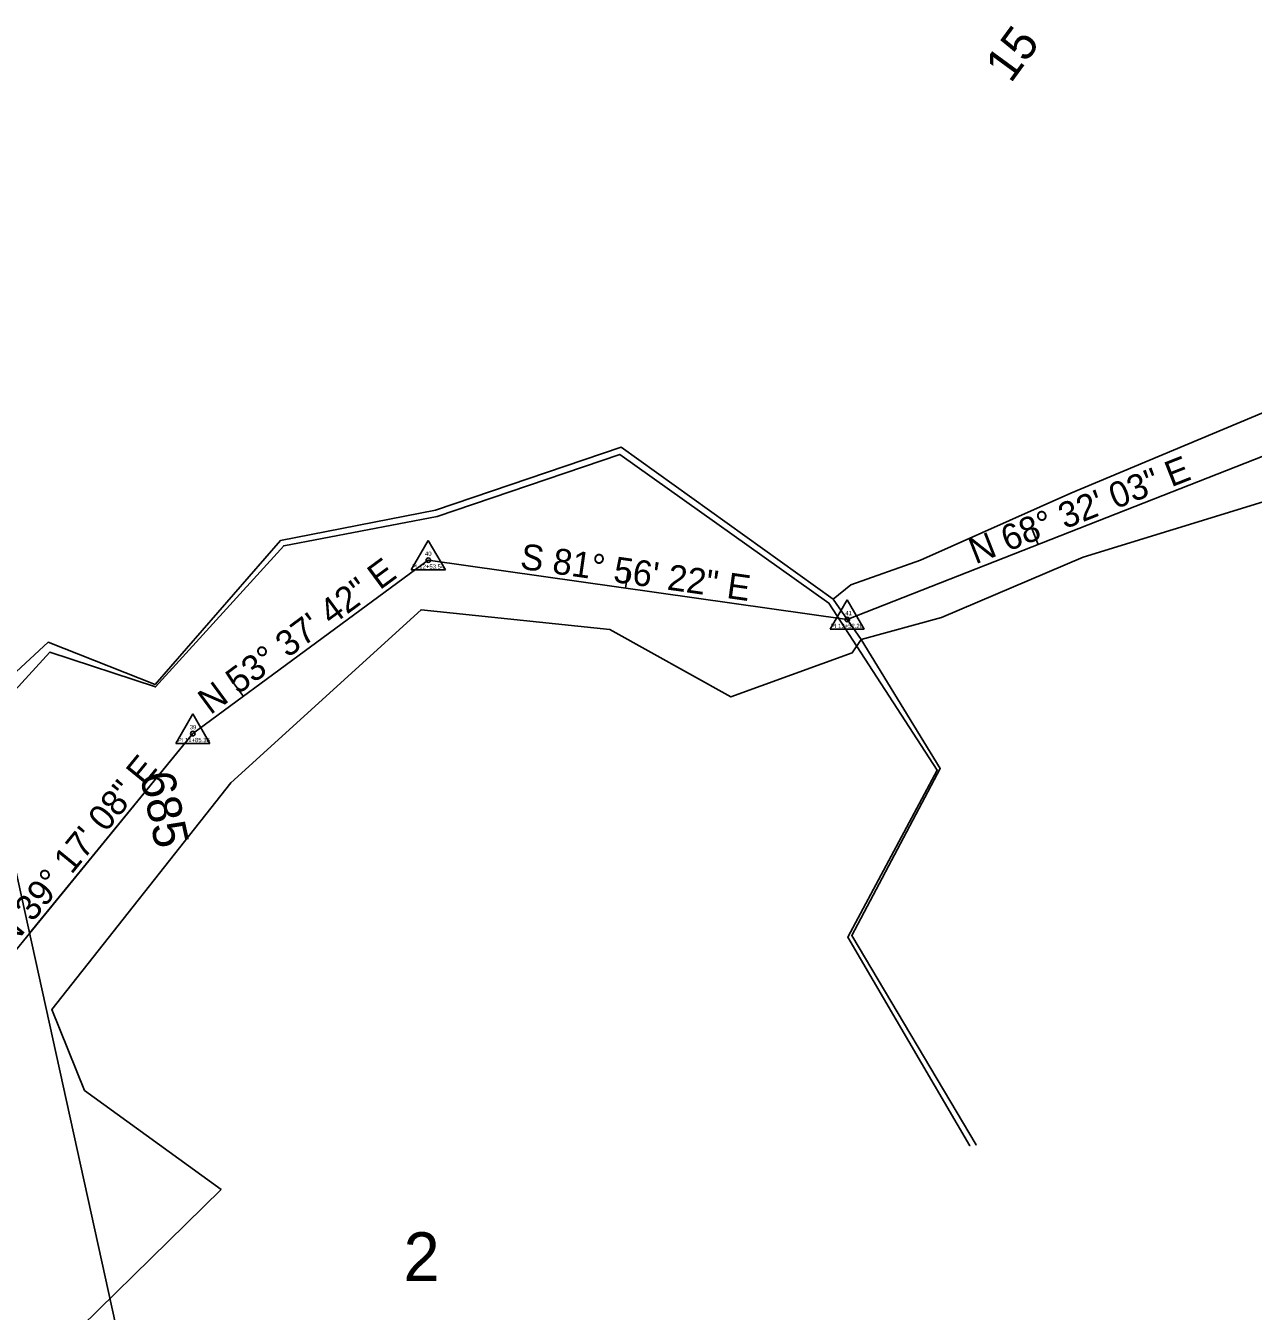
# Model space of a CAD drawing. Extents: x 2519952 to 2531965, y 848341 to 887632.
# Drawn here: x 2521629.5 to 2521915.7, y 869290.2 to 869589.9 of the extents above; entities that cross this region are included whole.
import ezdxf

# ---------------------------------------------------------------- set-up
doc = ezdxf.new("R2010")
doc.units = 0
for name, color, linetype in [('RD_EX_DV_Prop', 7, 'Continuous'), ('RD_EX_DV_TX_Prop', 7, 'Continuous'), ('RD_EX_H2O', 7, 'Continuous'), ('RD_EX_Misc', 7, 'Continuous'), ('RD_EX_RW', 7, 'Continuous'), ('RD_HC_Cl', 7, 'Continuous'), ('RD_HC_Data', 7, 'Continuous'), ('RD_HC_Data_Tic', 7, 'Continuous'), ('RD_HC_TX_Sta50', 7, 'Continuous'), ('RD_HC_txCode', 7, 'Continuous'), ('RD_SMD_Locator', 7, 'Continuous')]:
    doc.layers.add(name, color=color, linetype=linetype)

msp = doc.modelspace()

# ---------------------------------------------------------------- linework, layer by layer
at = {"layer": 'RD_EX_DV_Prop'}
for p, q in [((2521821.08, 869451.49), (2521934.22, 869495.99)), ((2521668.49, 869424.89), (2521723.39, 869465.33)), ((2521723.39, 869465.33), (2521821.08, 869451.49)), ((2521614.98, 869448.38), (2521679.49, 869155.4)), ((2521630.4, 869378.34), (2521668.49, 869424.89))]:
    msp.add_line(p, q, dxfattribs=at)
at = {"layer": 'RD_EX_H2O'}
for points in [[(2521817.75, 869456.23), (2521821.94, 869459.6), (2521838.16, 869465.32), (2521873.21, 869480.91), (2521930.21, 869504.82), (2521974.22, 869569.34)], [(2521849.68, 869328.81), (2521821.2, 869377.45), (2521842.05, 869416.38), (2521816.78, 869455.3), (2521768.08, 869489.96), (2521725.44, 869475.49), (2521689.67, 869468.67), (2521659.81, 869435.76), (2521635.15, 869443.9), (2521615.49, 869422.46), (2521611.76, 869370.27)], [(2521630.07, 869274.49), (2521675.08, 869318.6), (2521643.26, 869341.7), (2521635.64, 869360.59), (2521677.34, 869413.41), (2521721.72, 869453.75), (2521765.69, 869449.13), (2521793.89, 869433.43), (2521822.22, 869443.75), (2521824.35, 869446.83), (2521843.06, 869451.95), (2521876.06, 869465.98), (2521939.06, 869485.33)]]:
    msp.add_lwpolyline(points, dxfattribs=at)
at = {"layer": 'RD_EX_Misc'}
msp.add_lwpolyline([(2521851.13, 869329.01), (2521822.13, 869377.81), (2521842.77, 869416.73), (2521824.35, 869446.83), (2521817.75, 869456.23), (2521768.36, 869491.64), (2521725.07, 869476.94), (2521688.96, 869469.91), (2521659.69, 869436.33), (2521634.79, 869446.17), (2521612.48, 869425.6), (2521606.21, 869372.94)], dxfattribs=at)
at = {"layer": 'RD_EX_RW'}
msp.add_line((2521614.98, 869448.38), (2521679.5, 869155.4), dxfattribs=at)
at = {"layer": 'RD_HC_Cl'}
for p, q in [((2521821.08, 869451.49), (2521934.22, 869495.99)), ((2521668.49, 869424.89), (2521723.39, 869465.33)), ((2521723.39, 869465.33), (2521821.08, 869451.49)), ((2521620.93, 869366.76), (2521668.49, 869424.89))]:
    msp.add_line(p, q, dxfattribs=at)
at = {"layer": 'RD_HC_Data'}
for p, q in [((2521719.42, 869463.04), (2521723.39, 869469.91)), ((2521723.39, 869469.91), (2521727.36, 869463.04)), ((2521719.42, 869463.04), (2521727.36, 869463.04)), ((2521817.1, 869449.2), (2521821.08, 869456.08)), ((2521821.08, 869456.08), (2521825.05, 869449.2)), ((2521817.1, 869449.2), (2521825.05, 869449.2)), ((2521664.52, 869422.6), (2521668.49, 869429.48)), ((2521668.49, 869429.48), (2521672.46, 869422.6)), ((2521664.52, 869422.6), (2521672.46, 869422.6))]:
    msp.add_line(p, q, dxfattribs=at)
for centre in [(2521723.39, 869465.33), (2521821.08, 869451.49), (2521668.49, 869424.89)]:
    msp.add_circle(centre, 0.529, dxfattribs=at)
at = {"layer": 'RD_HC_Data_Tic'}
for p, q in [((2521865.56, 869468.98), (2521864.09, 869472.71)), ((2521769.39, 869458.81), (2521769.95, 869462.77)), ((2521680.28, 869433.57), (2521677.9, 869436.79))]:
    msp.add_line(p, q, dxfattribs=at)
at = {"layer": 'RD_SMD_Locator'}
for centre in [(2521768.36, 869491.64), (2521768.08, 869489.96), (2521873.21, 869480.91), (2521725.07, 869476.94), (2521725.44, 869475.49), (2521688.96, 869469.91), (2521689.67, 869468.67), (2521723.39, 869465.33), (2521838.16, 869465.32), (2521876.06, 869465.98), (2521821.94, 869459.6), (2521816.78, 869455.3), (2521817.75, 869456.23), (2521817.75, 869456.23), (2521721.72, 869453.75), (2521821.08, 869451.49), (2521843.06, 869451.95), (2521765.69, 869449.13), (2521634.79, 869446.17), (2521824.35, 869446.83), (2521824.35, 869446.83), (2521635.15, 869443.9), (2521822.22, 869443.75), (2521659.69, 869436.33), (2521659.81, 869435.76), (2521793.89, 869433.43), (2521668.49, 869424.89), (2521842.05, 869416.38), (2521842.77, 869416.73), (2521677.34, 869413.41), (2521821.2, 869377.45), (2521822.13, 869377.81), (2521635.64, 869360.59), (2521643.26, 869341.7), (2521849.68, 869328.81), (2521851.13, 869329.01), (2521675.08, 869318.6)]:
    msp.add_circle(centre, 0.001, dxfattribs=at)

# ---------------------------------------------------------------- texts
at = {"layer": 'RD_EX_DV_TX_Prop'}
msp.add_text('2', height=11.32, dxfattribs=at).set_placement((2521717.62, 869297.3))
at = {"layer": 'RD_HC_Data'}
for s, rotation, p in [('N 68%%d 32\' 03" E', 21.4658, (2521850.95, 869464.32)), ('S 81%%d 56\' 22" E', 351.9395, (2521744.59, 869463.34)), ('N 53%%d 37\' 42" E', 36.3717, (2521672.57, 869429.14)), ('N 39%%d 17\' 08" E', 50.7144, (2521626.02, 869374.56))]:
    msp.add_text(s, height=6, rotation=rotation, dxfattribs=at).set_placement(p)
at = {"layer": 'RD_HC_TX_Sta50'}
for s, rotation, p in [('15', 53.787, (2521859.17, 869576.3)), ('685', 282.4185, (2521656.09, 869415.14))]:
    msp.add_text(s, height=8, rotation=rotation, dxfattribs=at).set_placement(p)
at = {"layer": 'RD_HC_txCode'}
for s, p in [('40', (2521722.62, 869466.33)), ('PI 12+53.54', (2521719.61, 869463.33)), ('41', (2521820.63, 869452.49)), ('PI 13+52.20', (2521817.26, 869449.49)), ('39', (2521667.76, 869425.89)), ('PI 11+85.36', (2521664.97, 869422.89))]:
    msp.add_text(s, height=1, dxfattribs=at).set_placement(p)

doc.saveas('drawing.dxf')
